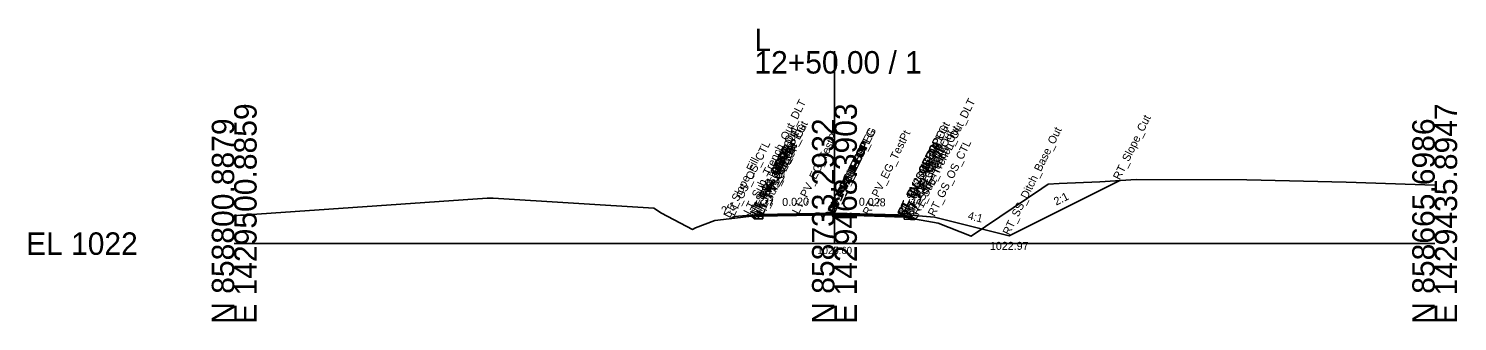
# Model space of a CAD drawing. Extents: x -26 to 153, y -10 to 13058.
# Drawn here: x -25.7 to 152.8, y 1990.3 to 2026.8 of the extents above; entities that cross this region are included whole.
import ezdxf

# ---------------------------------------------------------------- set-up
doc = ezdxf.new("R2010")
doc.units = 0
for name, color, linetype in [('Default', 7, 'Continuous'), ('Exist Cross Section Cell', 7, 'Continuous'), ('Exist XS Ground Line', 7, 'Continuous'), ('Prop CMT Pvmt Course 1', 7, 'Continuous'), ('Prop CMT Pvmt Course 1 Wedge', 7, 'Continuous'), ('Prop CMT Pvmt Course 2', 7, 'Continuous'), ('Prop CMT Pvmt Course 2 Wedge', 7, 'Continuous'), ('Prop CMT Pvmt Surface', 7, 'Continuous'), ('Prop CMT Pvmt Surface Shoulder', 7, 'Continuous'), ('Prop CMT Pvmt Wedge Surface 1', 7, 'Continuous'), ('Prop CMT Pvmt Wedge Surface 2', 7, 'Continuous'), ('Prop CMT Shld Paved Course 1', 7, 'Continuous'), ('Prop CMT Shld Paved Course 2', 7, 'Continuous'), ('Prop CMT Slope Grass', 7, 'Continuous'), ('Prop CMT Subgrade Daylight Point', 7, 'Continuous'), ('Prop CMT Subgrade Earthwork', 7, 'Continuous'), ('Prop XS Ditch Standard Text', 7, 'Continuous'), ('Prop XS Dump Level', 7, 'Continuous'), ('Prop XS SE Text', 7, 'Continuous'), ('Prop XS Side Slope Text', 7, 'Continuous')]:
    doc.layers.add(name, color=color, linetype=linetype)

msp = doc.modelspace()

# ---------------------------------------------------------------- linework, layer by layer
at = {"layer": 'Exist Cross Section Cell'}
for p, q in [((75, 2000), (75, 2024)), ((0, 2000), (75, 2000)), ((75, 2000), (150, 2000))]:
    msp.add_line(p, q, dxfattribs=at)
at = {"layer": 'Exist XS Ground Line'}
msp.add_lwpolyline([(0, 2003.48), (0.77, 2003.54), (1.21, 2003.56), (1.64, 2003.58), (17.83, 2004.7), (31.6, 2005.65), (32.36, 2005.65), (52.42, 2004.43), (53.37, 2003.81), (57.27, 2001.77), (57.64, 2001.96), (60.06, 2002.87), (61.13, 2003.01), (66.05, 2003.59), (72.3, 2003.6), (74.89, 2003.6), (81.28, 2003.38), (83.72, 2003.28), (87.95, 2002.54), (92.07, 2000.91), (100.93, 2006.89), (101.72, 2007.42), (103.09, 2007.5), (108.16, 2007.71), (112.69, 2008), (126.54, 2007.94), (138.94, 2007.68), (150, 2007.28)], dxfattribs=at)
at = {"layer": 'Prop CMT Pvmt Course 1'}
for points in [[(75, 2003.81), (65.5, 2003.62)], [(65.5, 2003.62), (65.5, 2003.41)], [(65.5, 2003.41), (66.05, 2003.42)], [(66.05, 2003.51), (75, 2003.69)], [(66.05, 2003.42), (66.05, 2003.51)], [(75, 2003.6), (75, 2003.81)], [(75, 2003.81), (84.5, 2003.55)], [(75, 2003.6), (75, 2003.81)], [(75, 2003.69), (75, 2003.6), (75, 2003.6)], [(83.72, 2003.44), (75, 2003.69)], [(75, 2003.69), (75, 2003.6), (75, 2003.6)], [(83.72, 2003.36), (83.72, 2003.44)], [(84.5, 2003.34), (83.72, 2003.36)], [(84.5, 2003.55), (84.5, 2003.34)]]:
    msp.add_lwpolyline(points, dxfattribs=at)
at = {"layer": 'Prop CMT Pvmt Course 1 Wedge'}
for points in [[(70.76, 2003.6), (72.3, 2003.63)], [(75, 2003.6), (74.89, 2003.6), (72.3, 2003.6), (70.76, 2003.6)], [(72.3, 2003.63), (74.89, 2003.68), (75, 2003.69)], [(75, 2003.69), (75, 2003.6)], [(75, 2003.69), (81.28, 2003.51), (83.72, 2003.44)], [(75, 2003.6), (75, 2003.69)], [(83.72, 2003.32), (81.28, 2003.39), (80.09, 2003.42), (75, 2003.6)], [(83.72, 2003.44), (83.72, 2003.32), (83.72, 2003.32)]]:
    msp.add_lwpolyline(points, dxfattribs=at)
at = {"layer": 'Prop CMT Pvmt Course 2'}
for points in [[(66.05, 2003.42), (65.5, 2003.41)], [(65.5, 2003.41), (65.5, 2003.08)], [(66.05, 2003.09), (66.05, 2003.42)], [(83.72, 2003.03), (83.72, 2003.36)], [(83.72, 2003.36), (84.5, 2003.34)], [(84.5, 2003.34), (84.5, 2003)], [(65.5, 2003.08), (66.05, 2003.09)], [(84.5, 2003), (83.72, 2003.03)]]:
    msp.add_lwpolyline(points, dxfattribs=at)
at = {"layer": 'Prop CMT Pvmt Course 2 Wedge'}
for points in [[(75, 2003.6), (74.89, 2003.6), (74.84, 2003.6)], [(74.84, 2003.6), (74.89, 2003.6)], [(74.89, 2003.6), (75, 2003.6)], [(75, 2003.6), (75, 2003.6)], [(75, 2003.6), (81.28, 2003.43), (83.72, 2003.36)], [(83.72, 2003.28), (81.28, 2003.38), (75, 2003.6)], [(75, 2003.6), (75, 2003.6)], [(83.72, 2003.36), (83.72, 2003.28), (83.72, 2003.28)]]:
    msp.add_lwpolyline(points, dxfattribs=at)
at = {"layer": 'Prop CMT Pvmt Surface'}
for points in [[(75, 2003.81), (65.5, 2003.62)], [(75, 2003.81), (84.5, 2003.55)]]:
    msp.add_lwpolyline(points, dxfattribs=at)
at = {"layer": 'Prop CMT Pvmt Surface Shoulder'}
for points in [[(65.5, 2003.62), (65.5, 2003.62)], [(84.5, 2003.55), (84.5, 2003.55)]]:
    msp.add_lwpolyline(points, dxfattribs=at)
at = {"layer": 'Prop CMT Pvmt Wedge Surface 1'}
for points in [[(65.5, 2003.41), (65.5, 2003.62)], [(66.05, 2003.42), (65.5, 2003.41)], [(75, 2003.69), (66.05, 2003.51)], [(66.05, 2003.51), (66.05, 2003.42)], [(75, 2003.69), (83.72, 2003.44)], [(83.72, 2003.44), (83.72, 2003.36)], [(83.72, 2003.36), (84.5, 2003.34)], [(84.5, 2003.34), (84.5, 2003.55)]]:
    msp.add_lwpolyline(points, dxfattribs=at)
at = {"layer": 'Prop CMT Pvmt Wedge Surface 2'}
for points in [[(65.5, 2003.41), (65.5, 2003.62)], [(75, 2003.6), (65.5, 2003.41)], [(75, 2003.6), (84.5, 2003.34)], [(84.5, 2003.34), (84.5, 2003.55)]]:
    msp.add_lwpolyline(points, dxfattribs=at)
at = {"layer": 'Prop CMT Shld Paved Course 1'}
for points in [[(65.5, 2003.62), (65.29, 2003.41)], [(65.29, 2003.41), (65.5, 2003.41)], [(65.5, 2003.62), (65.5, 2003.62)], [(65.5, 2003.41), (65.5, 2003.62)], [(84.5, 2003.55), (84.5, 2003.55)], [(84.5, 2003.55), (84.71, 2003.33)], [(84.5, 2003.34), (84.5, 2003.55)], [(84.71, 2003.33), (84.5, 2003.34)]]:
    msp.add_lwpolyline(points, dxfattribs=at)
at = {"layer": 'Prop CMT Shld Paved Course 2'}
for points in [[(65.29, 2003.41), (64.95, 2003.07)], [(65.5, 2003.41), (65.29, 2003.41)], [(65.29, 2003.41), (65.29, 2003.41)], [(65.5, 2003.08), (65.5, 2003.41)], [(84.5, 2003.34), (84.71, 2003.33)], [(84.5, 2003), (84.5, 2003.34)], [(84.71, 2003.33), (84.71, 2003.33)], [(84.71, 2003.33), (85.05, 2002.99)], [(64.95, 2003.07), (65.5, 2003.08)], [(85.05, 2002.99), (84.5, 2003)]]:
    msp.add_lwpolyline(points, dxfattribs=at)
at = {"layer": 'Prop CMT Slope Grass'}
for points in [[(84.5, 2003.55), (87.5, 2003.31), (96.85, 2000.97), (110.65, 2007.87)], [(65.5, 2003.62), (62.5, 2003.38), (61.95, 2003.11)]]:
    msp.add_lwpolyline(points, dxfattribs=at)
at = {"layer": 'Prop CMT Subgrade Earthwork'}
for points in [[(64.95, 2003.07), (64.48, 2003.54)], [(66.05, 2003.09), (66.07, 2003.59)], [(83.72, 2003.03), (83.7, 2003.28)], [(85.05, 2002.99), (85.52, 2003.46)], [(65.5, 2003.08), (64.95, 2003.07)], [(66.05, 2003.09), (65.5, 2003.08)], [(83.72, 2003.03), (84.5, 2003)], [(84.5, 2003), (85.05, 2002.99)]]:
    msp.add_lwpolyline(points, dxfattribs=at)

# ---------------------------------------------------------------- texts
at = {"layer": 'Default'}
msp.add_text('-', height=0.0001, dxfattribs=at).set_placement((0, 2000))
at = {"layer": 'Exist Cross Section Cell'}
for s, p in [('L', (65, 2024)), ('12+50.00 / 1', (65, 2021.2)), ('EL 1022', (-26, 1998.6))]:
    msp.add_text(s, height=2.8, dxfattribs=at).set_placement(p)
for s, p in [('E 1429500.8859', (2.8, 1990)), ('E 1429468.3903', (77.8, 1990)), ('E 1429435.8947', (152.8, 1990)), ('N 858800.8879', (0, 1990)), ('N 858733.2932', (75, 1990)), ('N 858665.6986', (150, 1990))]:
    msp.add_text(s, height=2.8, rotation=90, dxfattribs=at).set_placement(p)
at = {"layer": 'Prop CMT Subgrade Daylight Point'}
msp.add_text('1025.60', height=0.9, dxfattribs=at).set_placement((72.85, 1998.7))
at = {"layer": 'Prop XS Ditch Standard Text'}
msp.add_text('1022.97', height=1, dxfattribs=at).set_placement((94.42, 1999.22))
at = {"layer": 'Prop XS Dump Level'}
for s, p in [('LT_Sub_Trench_Out_DLT', (64.48, 2003.54)), ('RT_Sub_Trench_Out_DLT', (85.52, 2003.46)), ('RT_Slope_Cut', (110.65, 2007.87)), ('LT_Sub_Trench_Out', (64.95, 2003.07)), ('LT_PS2_Shelf_Out', (65.29, 2003.41)), ('LT_PV_OEEOP_EG', (66.05, 2003.59)), ('LT_PV_Sub_Tie_Out', (66.07, 2003.59)), ('LT_PV_EG_TestPt', (70.53, 2003.6)), ('RT_PV_IEEOP_EG', (75, 2003.6)), ('LT_PV_IEEOP_EG', (75, 2003.6)), ('RT_PV_EG_TestPt', (79.36, 2003.44)), ('RT_PV_Sub_Tie_Out', (83.7, 2003.28)), ('RT_PV_OEEOP_EG', (83.72, 2003.28)), ('RT_PS2_Shelf_Out', (84.71, 2003.33)), ('RT_Sub_Trench_Out', (85.05, 2002.99)), ('RT_SS_Ditch_Base_Out', (96.85, 2000.97)), ('LT_GS_OS_CTL', (62.5, 2003.38)), ('LT_PS2_OEOP', (65.29, 2003.41)), ('LT_PV1_OEOT', (65.5, 2003.62)), ('LT_PS1_OEOP', (65.5, 2003.62)), ('LT_PV2_OEOT', (65.5, 2003.41)), ('LT_PV1_OEEOP', (66.05, 2003.51)), ('LT_PV2_OEEOP', (66.05, 2003.42)), ('LT_Sub_OEEOP', (66.05, 2003.09)), ('RT_PV1_IEEOP', (75, 2003.69)), ('RT_PV2_IEEOP', (75, 2003.6)), ('LT_PV1_IEEOP', (75, 2003.69)), ('LT_PV2_IEEOP', (75, 2003.6)), ('RT_PV1_OEEOP', (83.72, 2003.44)), ('RT_PV2_OEEOP', (83.72, 2003.36)), ('RT_Sub_OEEOP', (83.72, 2003.03)), ('RT_PV1_OEOT', (84.5, 2003.55)), ('RT_PS1_OEOP', (84.5, 2003.55)), ('RT_PV2_OEOT', (84.5, 2003.34)), ('RT_PS2_OEOP', (84.71, 2003.33)), ('RT_GS_OS_CTL', (87.5, 2003.31)), ('LT_Slope_Fill', (61.95, 2003.11)), ('LT_Sub_OEOT', (65.5, 2003.08)), ('RT_Sub_OEOT', (84.5, 2003)), ('PV1_PGL', (75, 2003.81)), ('PV2_PGL', (75, 2003.6))]:
    msp.add_text(s, height=1, rotation=63.5833, dxfattribs=at).set_placement(p)
at = {"layer": 'Prop XS SE Text'}
for s, rotation, p in [('0.020', 1.1458, (68.48, 2004.68)), ('0.028', 358.3961, (78.04, 2004.73))]:
    msp.add_text(s, height=1, rotation=rotation, dxfattribs=at).set_placement(p)
at = {"layer": 'Prop XS Side Slope Text'}
for s, rotation, p in [('2:1', 26.5651, (61.18, 2003.56)), ('2:1', 26.5651, (102.71, 2004.73)), ('4:1', 345.9638, (91.59, 2003.06))]:
    msp.add_text(s, height=1, rotation=rotation, dxfattribs=at).set_placement(p)

doc.saveas('drawing.dxf')
